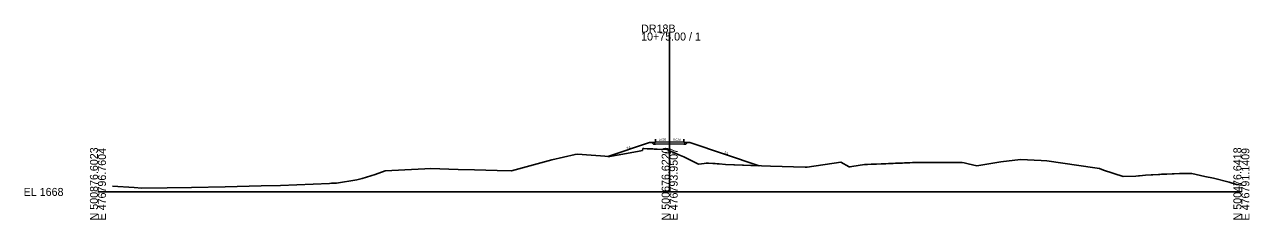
# Model space of a CAD drawing. Extents: x -26 to 403, y -10 to 2578.
# Drawn here: x -25.7 to 402.8, y -9.7 to 58.7 of the extents above; entities that cross this region are included whole.
import ezdxf

# ---------------------------------------------------------------- set-up
doc = ezdxf.new("R2010")
doc.units = 0
for name, color, linetype in [('Exist Cross Section Cell', 7, 'Continuous'), ('Exist XS Center Line Elevation Label', 7, 'Continuous'), ('Exist XS Ground Line', 7, 'Continuous'), ('Prop XS Earthwork Shape', 7, 'Continuous'), ('Prop XS EOT Tick Mark', 7, 'Continuous'), ('Prop XS Finish Grade', 7, 'Continuous'), ('Prop XS Finish Grade Earthwork', 7, 'Continuous'), ('Prop XS Finish Grade Pavement', 7, 'Continuous'), ('Prop XS Pvmt Edge Slope', 7, 'Continuous'), ('Prop XS SE Text', 7, 'Continuous'), ('Prop XS Shoulder Borrow Shape', 7, 'Continuous'), ('Prop XS Side Slope Text', 7, 'Continuous'), ('Prop XS Subgrade Earthwork', 7, 'Continuous')]:
    doc.layers.add(name, color=color, linetype=linetype)

msp = doc.modelspace()

# ---------------------------------------------------------------- linework, layer by layer
at = {"layer": 'Exist Cross Section Cell'}
for p, q in [((200, 0), (200, 55.88)), ((0, 0), (200, 0)), ((200, 0), (400, 0))]:
    msp.add_line(p, q, dxfattribs=at)
at = {"layer": 'Exist XS Ground Line'}
msp.add_lwpolyline([(5.08, 2.01), (12.68, 1.49), (15.37, 1.27), (24.18, 1.38), (32.76, 1.56), (44.56, 1.77), (57.08, 2.09), (63.81, 2.2), (81, 2.99), (81.71, 3.01), (83.48, 3.09), (90.62, 4.24), (92.38, 4.69), (96.93, 6.14), (100.42, 7.35), (112.07, 7.93), (114.41, 8.08), (116.28, 8.16), (126.03, 7.86), (131.69, 7.76), (139.68, 7.51), (144.72, 7.34), (158.75, 11.27), (166.93, 13.16), (167.73, 13.24), (178.98, 12.37), (182.37, 13.02), (189.31, 14.34), (190.47, 14.57), (190.64, 15.2), (190.98, 15.18), (192.08, 15.14), (192.6, 15.11), (194.12, 15.05), (194.56, 15.03), (195.03, 15.01), (195.61, 14.99), (199.13, 14.84), (200, 14.45), (201.72, 13.69), (203.23, 13.02), (204.4, 12.51), (204.99, 12.25), (210.12, 9.74), (211.18, 9.86), (212.09, 9.96), (212.81, 10.04), (213.53, 10.03), (215.1, 9.99), (215.93, 9.93), (216.59, 9.88), (217.36, 9.82), (219.49, 9.66), (235.26, 9), (247.41, 8.62), (248.07, 8.72), (259.87, 10.38), (262.75, 8.75), (263.19, 8.82), (263.78, 8.91), (268.21, 9.57), (269.19, 9.63), (270.46, 9.68), (270.88, 9.69), (271.75, 9.72), (272.36, 9.74), (273.97, 9.81), (275.67, 9.88), (276.51, 9.91), (278.24, 9.98), (278.95, 10.02), (280.71, 10.09), (281.46, 10.12), (282.13, 10.15), (283.98, 10.23), (284.95, 10.27), (285.77, 10.29), (286.58, 10.31), (288.56, 10.31), (288.96, 10.32), (290.88, 10.32), (291.45, 10.32), (292, 10.33), (294.01, 10.32), (294.55, 10.32), (296.45, 10.31), (298.51, 10.32), (298.93, 10.32), (299.33, 10.32), (300.33, 10.32), (301.33, 10.32), (301.71, 10.32), (302.32, 10.31), (303.05, 10.16), (304.42, 9.88), (307.45, 9.17), (315.88, 10.58), (322.7, 11.34), (329.94, 11.01), (331.91, 10.89), (348.76, 8.43), (350.32, 8.17), (351.72, 7.68), (358.7, 5.42), (363.12, 5.48), (363.97, 5.6), (364.4, 5.65), (366.49, 5.9), (368.48, 5.99), (368.99, 6.02), (370.95, 6.12), (371.48, 6.15), (372.03, 6.17), (373.1, 6.23), (373.66, 6.26), (373.97, 6.27), (375.84, 6.36), (376.46, 6.39), (378.31, 6.46), (378.96, 6.49), (379.62, 6.48), (381.45, 6.48), (382.27, 6.48), (382.63, 6.48), (387.25, 5.44), (390.22, 4.81), (395.67, 3.46), (398.25, 2.64), (400, 2.31)], dxfattribs=at)
at = {"layer": 'Prop XS Earthwork Shape'}
msp.add_lwpolyline([(212.81, 10.04), (213.53, 10.03), (215.1, 9.99), (215.93, 9.93), (216.59, 9.88), (217.36, 9.82), (219.49, 9.66), (231.36, 9.16), (207.02, 17.28), (206.27, 17.34), (205.69, 16.76), (205.01, 16.77), (200, 16.87), (194.99, 16.77), (194.31, 16.76), (193.73, 17.34), (192.98, 17.28), (178.39, 12.41), (178.98, 12.37), (182.37, 13.02), (189.31, 14.34), (190.47, 14.57), (190.64, 15.2), (190.98, 15.18), (192.08, 15.14), (192.6, 15.11), (194.12, 15.05), (194.56, 15.03), (195.03, 15.01), (195.61, 14.99), (199.13, 14.84), (200, 14.45), (201.72, 13.69), (203.23, 13.02), (204.4, 12.51), (204.99, 12.25), (210.12, 9.74), (211.18, 9.86), (212.09, 9.96)], close=True, dxfattribs=at)
at = {"layer": 'Prop XS EOT Tick Mark'}
for p, q in [((194.99, 17.44), (194.99, 18.44)), ((205.01, 17.44), (205.01, 18.44))]:
    msp.add_line(p, q, dxfattribs=at)
at = {"layer": 'Prop XS Finish Grade'}
for p, q in [((194.99, 17.44), (193.73, 17.34)), ((205.01, 17.44), (206.27, 17.34))]:
    msp.add_line(p, q, dxfattribs=at)
at = {"layer": 'Prop XS Finish Grade Earthwork'}
for p, q in [((192.98, 17.28), (178.39, 12.41)), ((193.73, 17.34), (192.98, 17.28)), ((206.27, 17.34), (207.02, 17.28)), ((207.02, 17.28), (231.36, 9.16))]:
    msp.add_line(p, q, dxfattribs=at)
at = {"layer": 'Prop XS Finish Grade Pavement'}
for p, q in [((194.99, 17.44), (200, 17.54)), ((200, 17.54), (205.01, 17.44))]:
    msp.add_line(p, q, dxfattribs=at)
at = {"layer": 'Prop XS Pvmt Edge Slope'}
for p, q in [((194.99, 17.44), (194.31, 16.76)), ((205.01, 17.44), (205.69, 16.76))]:
    msp.add_line(p, q, dxfattribs=at)
at = {"layer": 'Prop XS Shoulder Borrow Shape'}
for points in [[(194.99, 17.44), (194.31, 16.76), (193.73, 17.34)], [(205.69, 16.76), (206.27, 17.34), (205.01, 17.44)]]:
    msp.add_lwpolyline(points, close=True, dxfattribs=at)
at = {"layer": 'Prop XS Subgrade Earthwork'}
for p, q in [((194.31, 16.76), (193.73, 17.34)), ((205.69, 16.76), (206.27, 17.34)), ((194.99, 16.77), (194.31, 16.76)), ((200, 16.87), (194.99, 16.77)), ((205.01, 16.77), (200, 16.87)), ((205.01, 16.77), (205.69, 16.76))]:
    msp.add_line(p, q, dxfattribs=at)

# ---------------------------------------------------------------- texts
at = {"layer": 'Exist Cross Section Cell'}
for s, p in [('10+75.00 / 1', (190, 53.08)), ('DR18B', (190, 55.88)), ('EL 1668', (-26, -1.4))]:
    msp.add_text(s, height=2.8, dxfattribs=at).set_placement(p)
for s, p in [('N 500876.6023', (0, -10)), ('E 476796.7604', (2.8, -10)), ('N 500676.6220', (200, -10)), ('E 476793.9507', (202.8, -10)), ('N 500476.6418', (400, -10)), ('E 476791.1409', (402.8, -10))]:
    msp.add_text(s, height=2.8, rotation=90, dxfattribs=at).set_placement(p)
at = {"layer": 'Exist XS Center Line Elevation Label'}
msp.add_text('1682.45', height=0.75, dxfattribs=at).set_placement((198.23, 13.14))
at = {"layer": 'Prop XS SE Text'}
for rotation, p in [(1.1458, (196.2, 17.96)), (358.8542, (201.21, 18.01))]:
    msp.add_text('0.020', height=0.75, rotation=rotation, dxfattribs=at).set_placement(p)
at = {"layer": 'Prop XS Side Slope Text'}
for rotation, p in [(18.4349, (185.03, 14.99)), (341.5651, (219.07, 13.58))]:
    msp.add_text('3:1', height=0.75, rotation=rotation, dxfattribs=at).set_placement(p)

doc.saveas('drawing.dxf')
